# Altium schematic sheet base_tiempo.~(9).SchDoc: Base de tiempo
size A4; Revision: 1
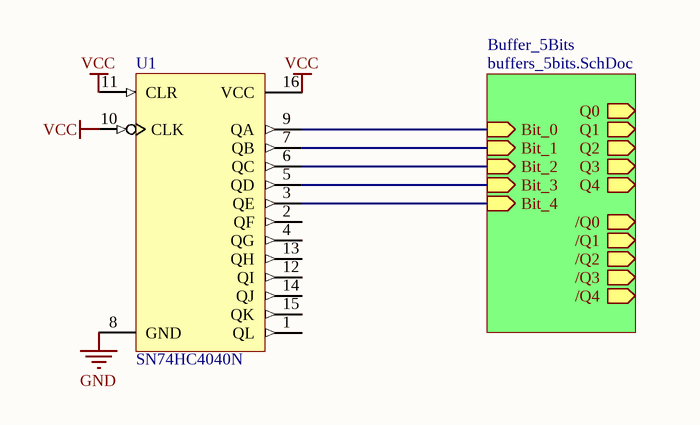
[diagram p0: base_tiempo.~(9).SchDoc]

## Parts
U1  SN74HC4040N  [N016]

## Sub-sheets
Buffer_5Bits = buffers_5bits.SchDoc: Bit_0 (in), Bit_1 (in), Bit_2 (in), Bit_3 (in), Bit_4 (in), Q0 (out), Q1 (out), Q2 (out), Q3 (out), Q4 (out), /Q0 (out), /Q1 (out), /Q2 (out), /Q3 (out), /Q4 (out)

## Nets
GND: U1.8(GND)
VCC: U1.10(CLK) U1.11(CLR) U1.16(VCC)
NetU1_3: U1.3(QE) ; sheet Buffer_5Bits/Bit_4
NetU1_5: U1.5(QD) ; sheet Buffer_5Bits/Bit_3
NetU1_6: U1.6(QC) ; sheet Buffer_5Bits/Bit_2
NetU1_7: U1.7(QB) ; sheet Buffer_5Bits/Bit_1
NetU1_9: U1.9(QA) ; sheet Buffer_5Bits/Bit_0

Not connected (* = marked no-connect by the designer): U1 1(QL) 2(QF) 4(QG) 12(QI) 13(QH) 14(QJ) 15(QK)

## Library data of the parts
U1 = SN74HC4040N: 12-Bit Asynchronous Binary Counter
